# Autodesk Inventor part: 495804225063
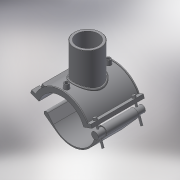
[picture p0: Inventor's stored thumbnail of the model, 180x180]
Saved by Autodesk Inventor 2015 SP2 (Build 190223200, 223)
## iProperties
Created: 2017-07
Part Number: 495804225063
Material: Generic
Description: PLASSON BRANCH SADDLE 225-63
Document SubType Name: Modeling
Designer: KIM
Density: 1 g/cm^3
Appearance: Default
Author: KIM
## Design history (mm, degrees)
derived "495804.ipt"
feature "Solid1::495804.ipt"
feature "Solid2::495804.ipt"
tag "TaggingFeature1"
body "Solid1"
body "Solid2"
other parameters: "d_" = 225, "B_" = 227, "H_" = 102, "L_" = 176, "d_t" = 6, "d_1" = 63, "H_1" = 85, "d1" = 259, "d148" = 5.625, "d160" = 5.625, "d0" = 225, "d2" = 295.1, "d3" = 56.25, "d4" = 176, "d5" = 0, "d6" = 0.1, "d8" = 0, "d19" = 6, "d20" = 6, "d21" = 105.6, "d23" = 0, "d24" = 52.8, "d26" = 0, "d27" = 3, "d28" = 3, "d29" = 3, "d30" = 75, "d31" = 6, "d32" = 0, "d33" = 0, "d34" = 0.6, "d40" = 134.68, "d41" = 69.3, "d43" = 0, "d45" = 0, "d47" = 231.5, "d48" = 63, "d50" = 0, "d70" = 15, "d72" = 0, "d73" = 6, "d75" = 5, "d76" = 0, "d77" = 11.25, "d78" = 142.5, "d79" = 15, "d80" = 70.4, "d82" = 5 deg, "d84" = 4, "d85" = 14, "d86" = 0, "d87" = 3, "d88" = 0, "d89" = 1, "d90" = 1, "d91" = 140.8, "d92" = 0, "d93" = 0.5, "d94" = 118.42105, "d96" = 264.18, "d97" = 3.52, "d98" = 0, "d102" = 1.89, "d103" = 50.4, "d105" = 0, "d109" = -34, "d117" = 0.63, "d120" = 140 deg, "d121" = 24.228, "d122" = 20 deg, "d123" = 518, "d124" = 155.4, "d126" = 0, "d143" = 236.25, "d150" = 40.5, "d159" = 6.8, "d161" = 5.625, "d162" = 105.6, "d163" = 0, "d167" = 45, "d168" = 117.72727, "d173" = 1, "d175" = 112.5, "d176" = 20 deg, "d177" = 15.75, "d178" = 34, "d180" = 0, "d185" = 57.2, "d186" = 57.2, "d187" = 129.5, "d188" = 10.2, "d189" = 15.75, "d190" = 0, "d191" = 194.25, "d200" = 17, "d202" = 0, "d216" = 158.4, "d217" = 0, "d221" = 65.12, "d222" = 15.75, "d223" = 9.45, "d224" = 112.5, "d225" = 9.45, "d227" = 32.4, "d230" = 139.5, "d236" = 20 deg, "d237" = 136.5, "d238" = 20 deg, "d239" = 15.75
